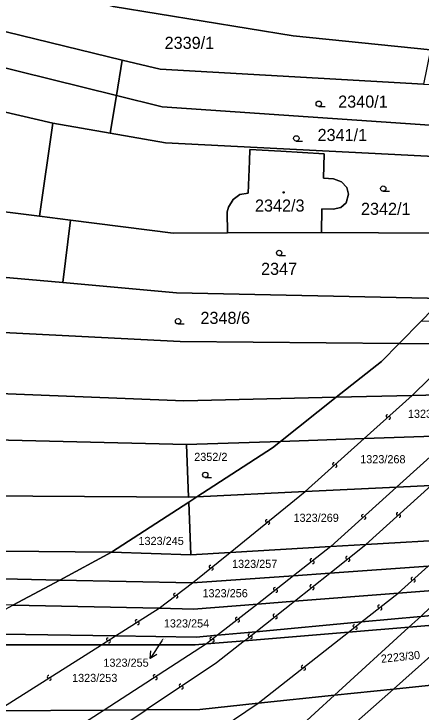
# Model space of a CAD drawing. Extents: x -596024 to -594475, y -1163820 to -1161957.
# Drawn here: x -595838.1 to -595781, y -1163161.8 to -1163063.8 of the extents above; entities that cross this region are included whole.
import ezdxf

# ---------------------------------------------------------------- set-up
doc = ezdxf.new("R2010")
doc.units = 0
for name, color, linetype in [('Level 1', 7, 'Continuous'), ('Level 13', 7, 'Continuous'), ('Level 3', 7, 'Continuous'), ('Level 4', 7, 'Continuous'), ('Level 5', 7, 'Continuous'), ('Level 57', 7, 'Continuous'), ('Level 60', 7, 'Continuous')]:
    doc.layers.add(name, color=color, linetype=linetype)

msp = doc.modelspace()

# ---------------------------------------------------------------- linework, layer by layer
at = {"layer": 'Level 1'}
for points in [[(-595779.65, -1163068.86), (-595798.9, -1163066.88), (-595824.16, -1163062.75), (-595839.42, -1163058.15)], [(-595869.68, -1163063.89), (-595823.71, -1163075.27)], [(-595841.12, -1163065.86), (-595822.9, -1163070.28)], [(-595870.77, -1163069.78), (-595863.08, -1163072.08), (-595832.64, -1163079.12)], [(-595822.9, -1163070.28), (-595823.71, -1163075.27)], [(-595780.6, -1163073.68), (-595817.56, -1163071.57), (-595822.9, -1163070.28)], [(-595823.71, -1163075.27), (-595824.57, -1163080.54)], [(-595759.26, -1163080.82), (-595817.3, -1163076.86), (-595823.71, -1163075.27)], [(-595834.51, -1163092.21), (-595832.64, -1163079.12)], [(-595824.57, -1163080.54), (-595832.64, -1163079.12)], [(-595762.63, -1163084.67), (-595816.82, -1163081.91), (-595824.57, -1163080.54)], [(-595808.11, -1163094.52), (-595808.16, -1163091.59), (-595807.96, -1163090.94), (-595807.34, -1163089.87), (-595806.4, -1163089.14), (-595805.2, -1163088.94), (-595805.01, -1163084.49), (-595804.99, -1163082.83), (-595800.65, -1163083.08), (-595794.54, -1163083.42), (-595794.64, -1163086.86), (-595793.25, -1163086.97), (-595792.11, -1163087.36), (-595791.39, -1163088.18), (-595791.13, -1163089.12), (-595791.49, -1163090.32), (-595792.2, -1163090.98), (-595793.28, -1163091.21), (-595794.87, -1163091.18), (-595794.91, -1163094.47)], [(-595834.51, -1163092.21), (-595852.58, -1163089.93), (-595890.49, -1163083.39)], [(-595830.15, -1163092.76), (-595834.51, -1163092.21)], [(-595830.15, -1163092.76), (-595831.2, -1163101.51)], [(-595830.15, -1163092.76), (-595815.73, -1163094.58), (-595808.11, -1163094.52)], [(-595808.11, -1163094.52), (-595794.91, -1163094.47)], [(-595770.92, -1163094.61), (-595794.91, -1163094.47)], [(-595831.2, -1163101.51), (-595840.28, -1163100.69)], [(-595777.88, -1163103.73), (-595815.28, -1163102.95), (-595831.2, -1163101.51)], [(-595784.03, -1163110.05), (-595780.92, -1163106.86)], [(-595921.21, -1163107.95), (-595850.78, -1163116.65), (-595814.22, -1163118.1), (-595792.85, -1163117.61)], [(-595784.03, -1163110.05), (-595814.78, -1163109.8), (-595841.47, -1163108.44)], [(-595784.03, -1163110.05), (-595786.49, -1163112.58), (-595792.85, -1163117.61)], [(-595784.03, -1163110.05), (-595774.84, -1163110.13)], [(-595921.08, -1163115.67), (-595850.43, -1163123.35), (-595813.86, -1163124.26)], [(-595770.72, -1163117.1), (-595782.22, -1163117.37)], [(-595792.85, -1163117.61), (-595800.68, -1163123.8)], [(-595782.22, -1163117.37), (-595792.85, -1163117.61)], [(-595788.92, -1163123.39), (-595776.34, -1163122.96)], [(-595800.68, -1163123.8), (-595813.86, -1163124.26)], [(-595800.68, -1163123.8), (-595801.8, -1163124.69), (-595812.42, -1163131.59)], [(-595800.68, -1163123.8), (-595788.92, -1163123.39)], [(-595813.58, -1163131.65), (-595850.06, -1163131.4), (-595909.96, -1163124.8)], [(-595813.58, -1163131.65), (-595813.86, -1163124.26)], [(-595779.55, -1163130), (-595784.39, -1163130.23)], [(-595797.22, -1163130.85), (-595812.42, -1163131.59)], [(-595784.39, -1163130.23), (-595797.22, -1163130.85)], [(-595920.68, -1163131.15), (-595849.96, -1163139.12), (-595824.38, -1163139.37)], [(-595813.58, -1163131.65), (-595812.42, -1163131.59)], [(-595812.42, -1163131.59), (-595813.55, -1163132.33)], [(-595813.55, -1163132.33), (-595824.38, -1163139.37)], [(-595813.55, -1163132.33), (-595813.24, -1163139.72)], [(-595920.55, -1163134.93), (-595849.5, -1163142.88), (-595831.65, -1163143.27)], [(-595788.71, -1163138.29), (-595775.74, -1163137.53)], [(-595807.76, -1163139.4), (-595793.63, -1163138.58)], [(-595793.63, -1163138.58), (-595788.71, -1163138.29)], [(-595824.38, -1163139.37), (-595831.65, -1163143.27)], [(-595824.38, -1163139.37), (-595813.24, -1163139.72)], [(-595813.24, -1163139.72), (-595807.76, -1163139.4)], [(-595779.96, -1163141.32), (-595793.78, -1163142.31)], [(-595798.85, -1163142.67), (-595813.04, -1163143.68)], [(-595793.78, -1163142.31), (-595798.85, -1163142.67)], [(-595831.65, -1163143.27), (-595838.24, -1163146.81)], [(-595813.04, -1163143.68), (-595831.65, -1163143.27)], [(-595784.18, -1163145.11), (-595776.89, -1163144.55)], [(-595776.89, -1163144.55), (-595780.61, -1163148.01), (-595781.01, -1163148.37)], [(-595798.74, -1163146.24), (-595784.18, -1163145.11)], [(-595803.91, -1163146.64), (-595812.87, -1163147.34), (-595817.72, -1163147.24)], [(-595803.91, -1163146.64), (-595798.74, -1163146.24)], [(-595817.72, -1163147.24), (-595838.24, -1163146.81)], [(-595772.48, -1163147.58), (-595781.01, -1163148.37)], [(-595781.01, -1163148.37), (-595789.3, -1163149.14)], [(-595782.66, -1163149.88), (-595781.01, -1163148.37)], [(-595789.3, -1163149.14), (-595804.13, -1163150.52)], [(-595784.85, -1163158.57), (-595776.55, -1163151.21), (-595774.29, -1163149.19)], [(-595782.66, -1163149.88), (-595774.29, -1163149.19)], [(-595804.13, -1163150.52), (-595809.5, -1163151.02)], [(-595805.74, -1163151.8), (-595791.13, -1163150.58)], [(-595793.11, -1163159.44), (-595782.66, -1163149.88)], [(-595791.13, -1163150.58), (-595782.66, -1163149.88)], [(-595823.85, -1163151.12), (-595845.99, -1163150.76)], [(-595809.5, -1163151.02), (-595812.49, -1163151.3), (-595823.85, -1163151.12)], [(-595825.81, -1163152.36), (-595849.5, -1163152.35)], [(-595811.05, -1163152.24), (-595812.64, -1163152.37), (-595825.81, -1163152.36)], [(-595811.05, -1163152.24), (-595805.74, -1163151.8)], [(-595768.41, -1163156.84), (-595784.85, -1163158.57)], [(-595803.8, -1163160.57), (-595793.11, -1163159.44)], [(-595793.11, -1163159.44), (-595801.38, -1163167.01), (-595801.73, -1163167.27)], [(-595793.63, -1163166.36), (-595784.85, -1163158.57)], [(-595793.11, -1163159.44), (-595784.85, -1163158.57)], [(-595803.8, -1163160.57), (-595812.02, -1163161.44), (-595819.53, -1163161.5)], [(-595840.48, -1163161.65), (-595825.44, -1163161.54)], [(-595825.44, -1163161.54), (-595819.53, -1163161.5)]]:
    msp.add_lwpolyline(points, dxfattribs=at)
at = {"layer": 'Level 13'}
for centre, start, end in [((-595785.692, -1163120.242), 79.31266, 311.41066), ((-595785.448, -1163120.517), 259.09821, 131.68821), ((-595793.192, -1163126.982), 79.32178, 311.41978), ((-595792.948, -1163127.257), 259.10733, 131.69733), ((-595784.252, -1163134.002), 79.51852, 311.61651), ((-595802.605, -1163134.976), 76.42154, 308.51954), ((-595789.133, -1163134.263), 79.26176, 311.85176), ((-595788.888, -1163134.538), 259.47621, 131.57421), ((-595784.007, -1163134.277), 259.30406, 131.89406), ((-595802.375, -1163135.263), 256.20709, 128.79709), ((-595796.353, -1163140.475), 75.23786, 307.82786), ((-595796.128, -1163140.766), 255.45232, 127.55031), ((-595791.353, -1163140.154), 75.78361, 307.88161), ((-595791.126, -1163140.445), 255.56916, 128.15916), ((-595810.515, -1163141.396), 76.40117, 308.49916), ((-595810.285, -1163141.683), 256.18671, 128.77671), ((-595782.192, -1163143.082), 79.29988, 311.39788), ((-595781.948, -1163143.357), 259.08542, 131.67543), ((-595801.493, -1163144.515), 75.27548, 307.86548), ((-595801.267, -1163144.806), 255.48993, 127.58793), ((-595796.373, -1163144.124), 75.76388, 307.86188), ((-595796.146, -1163144.415), 255.54943, 128.13943), ((-595815.49, -1163145.312), 74.63239, 306.73039), ((-595815.269, -1163145.607), 254.41794, 127.00794), ((-595786.853, -1163146.974), 75.57935, 307.67735), ((-595786.627, -1163147.265), 255.36489, 127.95489), ((-595806.823, -1163148.685), 75.23847, 307.82847), ((-595801.553, -1163148.235), 75.82453, 307.92252), ((-595801.326, -1163148.525), 255.61007, 128.20007), ((-595820.877, -1163149.023), 69.70461, 301.80261), ((-595820.682, -1163149.336), 249.49015, 122.08015), ((-595806.598, -1163148.976), 255.45293, 127.55092), ((-595790.333, -1163149.714), 75.57142, 307.66942), ((-595790.107, -1163150.005), 255.35696, 127.94696), ((-595824.927, -1163151.583), 69.69235, 301.79035), ((-595810.393, -1163151.485), 75.36445, 307.95445), ((-595810.167, -1163151.776), 255.5789, 127.6769), ((-595805.053, -1163151.015), 75.85852, 307.95652), ((-595804.826, -1163151.305), 255.64407, 128.23407), ((-595824.732, -1163151.896), 249.47789, 122.06789), ((-595797.583, -1163155.434), 75.62769, 307.72569), ((-595797.357, -1163155.725), 255.41323, 128.00323), ((-595818.349, -1163156.735), 70.03214, 302.62214), ((-595833.237, -1163156.853), 69.71739, 301.81539), ((-595833.042, -1163157.166), 249.50293, 122.09293), ((-595818.151, -1163157.046), 250.2466, 122.34459), ((-595814.702, -1163158.046), 70.88851, 303.47851), ((-595814.499, -1163158.354), 251.10297, 123.20097)]:
    msp.add_arc(centre, 0.184, start, end, dxfattribs=at)
at = {"layer": 'Level 3'}
for points in [[(-595782.22, -1163117.37), (-595774.84, -1163110.13)], [(-595788.92, -1163123.39), (-595782.22, -1163117.37)], [(-595776.34, -1163122.96), (-595784.39, -1163130.23)], [(-595797.22, -1163130.85), (-595788.92, -1163123.39)], [(-595788.71, -1163138.29), (-595779.55, -1163130)], [(-595807.76, -1163139.4), (-595797.22, -1163130.85)], [(-595784.39, -1163130.23), (-595793.63, -1163138.58)], [(-595793.63, -1163138.58), (-595798.85, -1163142.67)], [(-595793.78, -1163142.31), (-595788.71, -1163138.29)], [(-595813.04, -1163143.68), (-595807.76, -1163139.4)], [(-595784.18, -1163145.11), (-595779.96, -1163141.32)], [(-595798.85, -1163142.67), (-595803.91, -1163146.64)], [(-595798.74, -1163146.24), (-595793.78, -1163142.31)], [(-595817.72, -1163147.24), (-595813.04, -1163143.68)], [(-595789.3, -1163149.14), (-595784.18, -1163145.11)], [(-595803.91, -1163146.64), (-595809.5, -1163151.02)], [(-595804.13, -1163150.52), (-595798.74, -1163146.24)], [(-595823.85, -1163151.12), (-595817.72, -1163147.24)], [(-595791.13, -1163150.58), (-595789.3, -1163149.14)], [(-595805.74, -1163151.8), (-595804.13, -1163150.52)], [(-595803.8, -1163160.57), (-595791.13, -1163150.58)], [(-595825.81, -1163152.36), (-595823.85, -1163151.12)], [(-595809.5, -1163151.02), (-595811.05, -1163152.24)], [(-595840.48, -1163161.65), (-595825.81, -1163152.36)], [(-595811.05, -1163152.24), (-595825.44, -1163161.54)], [(-595805.74, -1163151.8), (-595809.66, -1163154.91), (-595819.53, -1163161.5)], [(-595815.49, -1163168.44), (-595803.8, -1163160.57)], [(-595825.44, -1163161.54), (-595836.21, -1163168.51)], [(-595830.02, -1163168.49), (-595819.53, -1163161.5)]]:
    msp.add_lwpolyline(points, dxfattribs=at)
at = {"layer": 'Level 5'}
for p, q in [((-595795.31, -1163076.79), (-595794.435, -1163076.79)), ((-595798.46, -1163081.64), (-595797.585, -1163081.64)), ((-595786.26, -1163088.7), (-595785.385, -1163088.7)), ((-595800.87, -1163097.73), (-595799.995, -1163097.73)), ((-595815.06, -1163107.32), (-595814.185, -1163107.32)), ((-595811.23, -1163128.88), (-595810.355, -1163128.88))]:
    msp.add_line(p, q, dxfattribs=at)
for centre, radius in [((-595795.31, -1163076.415), 0.375), ((-595798.46, -1163081.265), 0.375), ((-595786.26, -1163088.325), 0.375), ((-595800.24, -1163088.85), 0.09), ((-595800.24, -1163088.85), 0.0521), ((-595800.87, -1163097.355), 0.375), ((-595815.06, -1163106.945), 0.375), ((-595811.23, -1163128.505), 0.375)]:
    msp.add_circle(centre, radius, dxfattribs=at)
at = {"layer": 'Level 57'}
for p, q in [((-595817.23, -1163151.61), (-595817.344, -1163151.785)), ((-595817.344, -1163151.785), (-595818.98, -1163154.3))]:
    msp.add_line(p, q, dxfattribs=at)
msp.add_lwpolyline([(-595818.016, -1163153.734), (-595818.98, -1163154.3), (-595818.854, -1163153.189)], dxfattribs=at)
at = {"layer": 'Level 60'}
for points in [[(-595846.87, -1163047.06), (-595837.67, -1163049.21), (-595828.31, -1163051.33), (-595821.92, -1163052.7), (-595812.73, -1163054.87), (-595794.09, -1163059.15), (-595773.96, -1163063.72), (-595750.84, -1163064.39), (-595757.26, -1163072.39), (-595770.62, -1163069.8), (-595779.65, -1163068.86), (-595798.9, -1163066.88), (-595824.16, -1163062.75), (-595839.42, -1163058.15)], [(-595770.92, -1163094.61), (-595794.91, -1163094.47), (-595794.87, -1163091.18), (-595793.28, -1163091.21), (-595792.2, -1163090.98), (-595791.49, -1163090.32), (-595791.13, -1163089.12), (-595791.39, -1163088.18), (-595792.11, -1163087.36), (-595793.25, -1163086.97), (-595794.64, -1163086.86), (-595794.54, -1163083.42), (-595800.65, -1163083.08), (-595804.99, -1163082.83), (-595805.01, -1163084.49), (-595805.2, -1163088.94), (-595806.4, -1163089.14), (-595807.34, -1163089.87), (-595807.96, -1163090.94), (-595808.16, -1163091.59), (-595808.11, -1163094.52), (-595815.73, -1163094.58), (-595830.15, -1163092.76), (-595834.51, -1163092.21), (-595832.64, -1163079.12), (-595824.57, -1163080.54), (-595816.82, -1163081.91), (-595762.63, -1163084.67)]]:
    msp.add_lwpolyline(points, dxfattribs=at)
for points in [[(-595868.75, -1163057.97), (-595841.12, -1163065.86), (-595822.9, -1163070.28), (-595823.71, -1163075.27), (-595869.68, -1163063.89)], [(-595841.12, -1163065.86), (-595839.42, -1163058.15), (-595824.16, -1163062.75), (-595798.9, -1163066.88), (-595779.65, -1163068.86), (-595780.6, -1163073.68), (-595817.56, -1163071.57), (-595822.9, -1163070.28)], [(-595870.77, -1163069.78), (-595863.08, -1163072.08), (-595832.64, -1163079.12), (-595834.51, -1163092.21), (-595852.58, -1163089.93), (-595890.49, -1163083.39), (-595889.15, -1163076.51), (-595887.81, -1163076.72), (-595885.93, -1163066.94), (-595893.75, -1163065.36), (-595893.4, -1163064.07), (-595892.55, -1163064.26), (-595879.85, -1163067.57)], [(-595863.08, -1163072.08), (-595870.77, -1163069.78), (-595869.68, -1163063.89), (-595823.71, -1163075.27), (-595824.57, -1163080.54), (-595832.64, -1163079.12)], [(-595759.26, -1163080.82), (-595817.3, -1163076.86), (-595823.71, -1163075.27), (-595822.9, -1163070.28), (-595817.56, -1163071.57), (-595780.6, -1163073.68), (-595759.28, -1163074.91), (-595755.19, -1163076.19)], [(-595762.63, -1163084.67), (-595816.82, -1163081.91), (-595824.57, -1163080.54), (-595823.71, -1163075.27), (-595817.3, -1163076.86), (-595759.26, -1163080.82)], [(-595927.24, -1163084.46), (-595929.61, -1163076.65), (-595929.12, -1163076.73), (-595907.41, -1163080.47), (-595890.49, -1163083.39), (-595852.58, -1163089.93), (-595834.51, -1163092.21), (-595830.15, -1163092.76), (-595831.2, -1163101.51), (-595840.28, -1163100.69), (-595852, -1163099.63), (-595925.78, -1163089.31)], [(-595804.99, -1163082.83), (-595800.65, -1163083.08), (-595794.54, -1163083.42), (-595794.64, -1163086.86), (-595793.25, -1163086.97), (-595792.11, -1163087.36), (-595791.39, -1163088.18), (-595791.13, -1163089.12), (-595791.49, -1163090.32), (-595792.2, -1163090.98), (-595793.28, -1163091.21), (-595794.87, -1163091.18), (-595794.91, -1163094.47), (-595808.11, -1163094.52), (-595808.16, -1163091.59), (-595807.96, -1163090.94), (-595807.34, -1163089.87), (-595806.4, -1163089.14), (-595805.2, -1163088.94), (-595805.01, -1163084.49)], [(-595770.07, -1163095.69), (-595777.88, -1163103.73), (-595815.28, -1163102.95), (-595831.2, -1163101.51), (-595830.15, -1163092.76), (-595815.73, -1163094.58), (-595808.11, -1163094.52), (-595794.91, -1163094.47), (-595770.92, -1163094.61)], [(-595921.21, -1163107.95), (-595923.18, -1163100.06), (-595851.27, -1163107.94), (-595841.47, -1163108.44), (-595814.78, -1163109.8), (-595784.03, -1163110.05), (-595786.49, -1163112.58), (-595792.85, -1163117.61), (-595814.22, -1163118.1), (-595850.78, -1163116.65)], [(-595815.28, -1163102.95), (-595777.88, -1163103.73), (-595780.92, -1163106.86), (-595784.03, -1163110.05), (-595814.78, -1163109.8), (-595841.47, -1163108.44), (-595840.88, -1163104.53), (-595840.28, -1163100.69), (-595831.2, -1163101.51)], [(-595784.03, -1163110.05), (-595780.92, -1163106.86), (-595771.65, -1163107), (-595761.17, -1163107.16), (-595758.79, -1163107.2), (-595756.38, -1163106.95), (-595743.3, -1163105.57), (-595734.51, -1163104.65), (-595737.21, -1163107.41), (-595745.57, -1163108.52), (-595758.64, -1163110.26), (-595759.55, -1163110.25), (-595764.11, -1163110.22), (-595774.84, -1163110.13)], [(-595786.49, -1163112.58), (-595784.03, -1163110.05), (-595774.84, -1163110.13), (-595764.11, -1163110.22), (-595759.55, -1163110.25), (-595758.64, -1163110.26), (-595745.57, -1163108.52), (-595737.21, -1163107.41), (-595745.15, -1163115.51), (-595752.01, -1163116.21), (-595757.92, -1163116.81), (-595766.01, -1163116.99), (-595770.72, -1163117.1), (-595782.22, -1163117.37), (-595792.85, -1163117.61)], [(-595921.08, -1163115.67), (-595921.21, -1163107.95), (-595850.78, -1163116.65), (-595814.22, -1163118.1), (-595792.85, -1163117.61), (-595800.68, -1163123.8), (-595813.86, -1163124.26), (-595850.43, -1163123.35)], [(-595920.82, -1163123.6), (-595921.08, -1163115.67), (-595850.43, -1163123.35), (-595813.86, -1163124.26), (-595813.58, -1163131.65), (-595850.06, -1163131.4), (-595909.96, -1163124.8)], [(-595800.68, -1163123.8), (-595792.85, -1163117.61), (-595782.22, -1163117.37), (-595770.72, -1163117.1), (-595766.01, -1163116.99), (-595757.92, -1163116.81), (-595752.01, -1163116.21), (-595745.15, -1163115.51), (-595747.09, -1163117.49), (-595751.63, -1163121.57), (-595757.69, -1163122.31), (-595758.84, -1163122.35), (-595771.57, -1163122.79), (-595776.34, -1163122.96), (-595788.92, -1163123.39)], [(-595801.8, -1163124.69), (-595800.68, -1163123.8), (-595788.92, -1163123.39), (-595776.34, -1163122.96), (-595771.57, -1163122.79), (-595758.84, -1163122.35), (-595757.69, -1163122.31), (-595751.63, -1163121.57), (-595759.94, -1163129.05), (-595766.66, -1163129.38), (-595779.55, -1163130), (-595784.39, -1163130.23), (-595797.22, -1163130.85), (-595812.42, -1163131.59)], [(-595813.58, -1163131.65), (-595813.86, -1163124.26), (-595800.68, -1163123.8), (-595801.8, -1163124.69), (-595812.42, -1163131.59)], [(-595849.96, -1163139.12), (-595920.68, -1163131.15), (-595920.75, -1163127.32), (-595916.75, -1163127.71), (-595910.35, -1163128.34), (-595909.98, -1163125), (-595909.96, -1163124.8), (-595850.06, -1163131.4), (-595813.58, -1163131.65), (-595812.42, -1163131.59), (-595813.55, -1163132.33), (-595824.38, -1163139.37)], [(-595759.94, -1163129.05), (-595768.41, -1163136.67), (-595768.91, -1163137.13), (-595775.74, -1163137.53), (-595788.71, -1163138.29), (-595793.63, -1163138.58), (-595807.76, -1163139.4), (-595813.24, -1163139.72), (-595813.55, -1163132.33), (-595812.42, -1163131.59), (-595797.22, -1163130.85), (-595784.39, -1163130.23), (-595779.55, -1163130), (-595766.66, -1163129.38)], [(-595920.55, -1163134.93), (-595920.68, -1163131.15), (-595849.96, -1163139.12), (-595824.38, -1163139.37), (-595831.65, -1163143.27), (-595849.5, -1163142.88)], [(-595824.38, -1163139.37), (-595813.55, -1163132.33), (-595813.24, -1163139.72)], [(-595920.42, -1163138.76), (-595920.55, -1163134.93), (-595849.5, -1163142.88), (-595831.65, -1163143.27), (-595838.24, -1163146.81), (-595849.27, -1163146.58)], [(-595831.65, -1163143.27), (-595824.38, -1163139.37), (-595813.24, -1163139.72), (-595807.76, -1163139.4), (-595793.63, -1163138.58), (-595788.71, -1163138.29), (-595775.74, -1163137.53), (-595768.91, -1163137.13), (-595772.87, -1163140.81), (-595779.96, -1163141.32), (-595793.78, -1163142.31), (-595798.85, -1163142.67), (-595813.04, -1163143.68)], [(-595838.24, -1163146.81), (-595831.65, -1163143.27), (-595813.04, -1163143.68), (-595798.85, -1163142.67), (-595793.78, -1163142.31), (-595779.96, -1163141.32), (-595772.87, -1163140.81), (-595776.89, -1163144.55), (-595784.18, -1163145.11), (-595798.74, -1163146.24), (-595803.91, -1163146.64), (-595812.87, -1163147.34), (-595817.72, -1163147.24)], [(-595843.43, -1163149.6), (-595838.24, -1163146.81), (-595817.72, -1163147.24), (-595812.87, -1163147.34), (-595803.91, -1163146.64), (-595798.74, -1163146.24), (-595784.18, -1163145.11), (-595776.89, -1163144.55), (-595780.61, -1163148.01), (-595781.01, -1163148.37), (-595789.3, -1163149.14), (-595804.13, -1163150.52), (-595809.5, -1163151.02), (-595812.49, -1163151.3), (-595823.85, -1163151.12), (-595845.99, -1163150.76)], [(-595768.35, -1163143.89), (-595772.48, -1163147.58), (-595781.01, -1163148.37), (-595780.61, -1163148.01), (-595776.89, -1163144.55)], [(-595755.71, -1163155.5), (-595702.2, -1163146.07), (-595699.94, -1163152.23), (-595755.32, -1163162.05), (-595793.63, -1163166.36), (-595784.85, -1163158.57), (-595768.41, -1163156.84)], [(-595772.48, -1163147.58), (-595774.29, -1163149.19), (-595782.66, -1163149.88), (-595781.01, -1163148.37)], [(-595849.5, -1163152.35), (-595845.99, -1163150.76), (-595823.85, -1163151.12), (-595812.49, -1163151.3), (-595809.5, -1163151.02), (-595804.13, -1163150.52), (-595789.3, -1163149.14), (-595781.01, -1163148.37), (-595782.66, -1163149.88), (-595791.13, -1163150.58), (-595805.74, -1163151.8), (-595811.05, -1163152.24), (-595812.64, -1163152.37), (-595825.81, -1163152.36)], [(-595776.55, -1163151.21), (-595784.85, -1163158.57), (-595793.11, -1163159.44), (-595782.66, -1163149.88), (-595774.29, -1163149.19)], [(-595784.85, -1163158.57), (-595776.55, -1163151.21), (-595774.29, -1163149.19), (-595769.08, -1163148.76), (-595768.41, -1163156.84)], [(-595865.99, -1163159.78), (-595849.5, -1163152.35), (-595825.81, -1163152.36), (-595812.64, -1163152.37), (-595811.05, -1163152.24), (-595805.74, -1163151.8), (-595791.13, -1163150.58), (-595782.66, -1163149.88), (-595793.11, -1163159.44), (-595803.8, -1163160.57), (-595812.02, -1163161.44), (-595819.53, -1163161.5), (-595825.44, -1163161.54), (-595840.48, -1163161.65), (-595848.25, -1163161.71)], [(-595879.26, -1163165.66), (-595878.21, -1163165.3), (-595865.99, -1163159.78), (-595848.25, -1163161.71), (-595840.48, -1163161.65), (-595825.44, -1163161.54), (-595819.53, -1163161.5), (-595812.02, -1163161.44), (-595803.8, -1163160.57), (-595793.11, -1163159.44), (-595801.38, -1163167.01), (-595801.73, -1163167.27), (-595811.96, -1163168.43), (-595815.49, -1163168.44), (-595830.02, -1163168.49), (-595836.21, -1163168.51), (-595847.79, -1163168.55), (-595851.95, -1163168.17)], [(-595784.85, -1163158.57), (-595793.63, -1163166.36), (-595801.73, -1163167.27), (-595801.38, -1163167.01), (-595793.11, -1163159.44)]]:
    msp.add_lwpolyline(points, close=True, dxfattribs=at)

# ---------------------------------------------------------------- texts
at = {"layer": 'Level 4'}
for s, height, p in [('2339/1', 1.7, (-595816.939, -1163068.71)), ('2340/1', 1.7, (-595792.59, -1163076.96)), ('2341/1', 1.7, (-595795.48, -1163081.64)), ('2342/3', 1.7, (-595804.26, -1163091.55)), ('2342/1', 1.7, (-595789.39, -1163092.01)), ('2347', 1.7, (-595803.41, -1163100.43)), ('2348/6', 1.7, (-595811.913, -1163107.32)), ('1323/267', 1.14, (-595782.807, -1163120.5)), ('2352/2', 1.14, (-595812.79, -1163126.55)), ('1323/268', 1.14, (-595789.502, -1163126.88)), ('1323/269', 1.14, (-595798.86, -1163135.1)), ('1323/245', 1.14, (-595820.608, -1163138.35)), ('1323/257', 1.14, (-595807.484, -1163141.57)), ('1323/256', 1.14, (-595811.628, -1163145.69)), ('1323/254', 1.14, (-595817.048, -1163149.93)), ('1323/255', 0.1, (-595817.23, -1163151.61)), ('1323/253', 1.14, (-595829.929, -1163157.58))]:
    msp.add_text(s, height=height, dxfattribs=at).set_placement(p)
msp.add_text('2223/30', height=1.14, rotation=6.01263, dxfattribs=at).set_placement((-595786.532, -1163154.902))
at = {"layer": 'Level 57'}
msp.add_text('1323/255', height=1.14, dxfattribs=at).set_placement((-595825.531, -1163155.44))

doc.saveas('drawing.dxf')
